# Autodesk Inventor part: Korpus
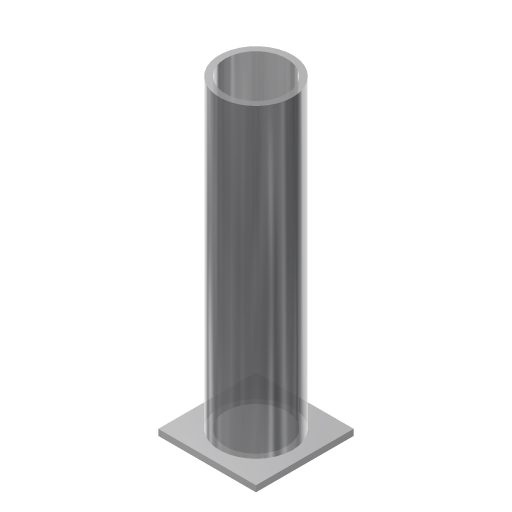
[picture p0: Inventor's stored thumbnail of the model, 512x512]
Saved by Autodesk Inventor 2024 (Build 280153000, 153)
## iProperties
Company: ATC
Created: 2023-03
Part Number: Korpus
Document SubType Name: Modeling
Designer: Andrzej Jaskulski
Density: 7.87 g/cm^3
Mass: 15.871 g
Surface Area: 161.27 cm^2
Volume: 15.871 cm^3
Material: Stal węglowa
Stock Number: Korpus
Appearance: Jasnoszare z połyskiem
Checked By: A.J.
Engr Approved By: Andrzej Jaskulski
Mfg Approved By: Andrzej Jaskulski
Authority: A.J.
Title: A.J.: Kurs R2024-MEP
Author: Andrzej Jaskulski
Revision Number: 1/24
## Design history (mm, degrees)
sketch "Szkic1"
  geometry: L1 (-16, 16)-(16, 16); L2 (16, 16)-(16, -16); L3 (16, -16)-(-16, -16); L4 (-16, -16)-(-16, 16); C1 r 10 at (0, 0); C2 r 12 at (0, 0); 2 further points
  constraints: 8 end point, 2 centre point, 2 midpoint, 2 parallel, 2 perpendicular, 1 coincident, 1 horizontal, 1 horizontal alignment, 1 vertical alignment, 1 other
  dimensions: "d0" = 20 diameter of C1; "d1" = 24 diameter of C2; "d6" = 32 distance of L2.end L3.end (computed from d1)
extrude "Wyciągnięcie proste1" new body sketch "Szkic1" distance "d2" = 100; taper "d3" = 0 deg
extrude "Wyciągnięcie proste2" join sketch "Szkic1" distance "d4" = 2; taper "d5" = 0 deg
extrude "Wyciągnięcie proste3" join sketch "Szkic1" distance "d7" = 2; taper "d8" = 0 deg
node "Bryła1"
node "Korpusy bryłowe"
node "Korpusy powierzchniowe"
